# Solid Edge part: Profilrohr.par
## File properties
Username: ahadarics
Dokumentum tartalom típus: 0
Author: ahadarics
Last saved by: ahadarics
Revision: 86
Sűrűség: 0,000 kg/m^3
Pontosság: 0,990
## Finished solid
Body 1: solid body, 6 faces, 6 edges, 0 vertices.
  Faces by surface: cone 2, cylinder 2, plane 2
  Edges by curve: circle 6
Bounding box of the edges (mm): 26.500 x 26.500 x 433.000, from (-13.25, -13.25, -411.5) to (13.25, 13.25, 21.5).
Cylindrical faces by radius (mm): R12.5 x1, R13.25 x1
Conical faces (half-angle, radius in mm at the cone's reference point): 15 deg R12.567 x2
Planar faces by outward normal: +z 1, -z 1
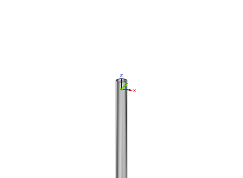
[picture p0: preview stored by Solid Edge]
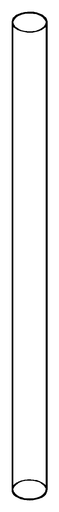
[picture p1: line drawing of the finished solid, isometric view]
